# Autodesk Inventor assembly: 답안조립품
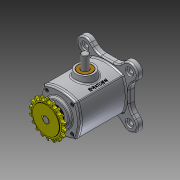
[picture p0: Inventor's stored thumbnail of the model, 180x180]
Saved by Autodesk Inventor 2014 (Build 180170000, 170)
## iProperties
Created: 2016-05
Part Number: 답안조립품
Document SubType Name: Assembly
Designer: Administrator
Author: Administrator
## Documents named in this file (11)
- C:\Users\Administrator\Desktop\460507V1021\답안조립품.iam
- C:\Users\Administrator\Desktop\460507V1021\1-본체.ipt
- C:\Users\Administrator\Desktop\460507V1021\M4x0.7x12.ipt
- C:\Users\Administrator\Desktop\460507V1021\베어링-6203.ipt
- C:\Users\Administrator\Desktop\460507V1021\부시.ipt
- C:\Users\Administrator\Desktop\460507V1021\스프로킷.ipt
- C:\Users\Administrator\Desktop\460507V1021\슬라이더.ipt
- C:\Users\Administrator\Desktop\460507V1021\오일실.ipt
- C:\Users\Administrator\Desktop\460507V1021\커버.ipt
- C:\Users\Administrator\Desktop\460507V1021\키5x5.ipt
- C:\Users\Administrator\Desktop\460507V1021\편심축.ipt
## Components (9 placed, 2 different names)
1. 1-본체:1
2. M4x0.7x12:1
3. M4x0.7x12:3
4. M4x0.7x12:4
5. M4x0.7x12:5
6. M4x0.7x12:2
7. M4x0.7x12:6
8. M4x0.7x12:7
9. M4x0.7x12:8
